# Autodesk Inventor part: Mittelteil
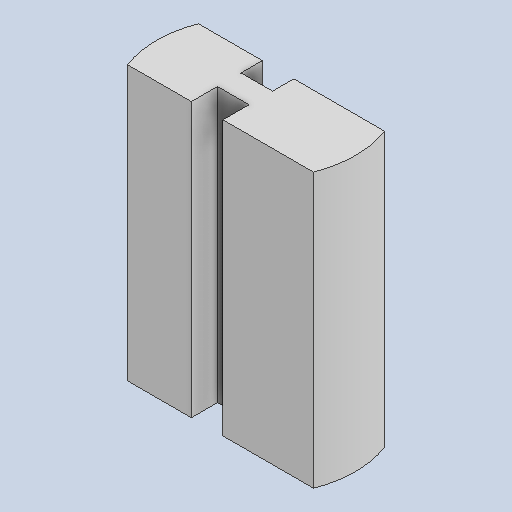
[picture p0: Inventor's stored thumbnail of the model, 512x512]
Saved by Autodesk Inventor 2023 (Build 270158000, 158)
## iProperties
Created: 2025-02
Part Number: Mittelteil
Material: Generisch
Document SubType Name: Modeling
Designer: MVM1
Density: 1 g/cm^3
Appearance: Vorgabe
Author: MVM1
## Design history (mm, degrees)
derived "Bauteil_Ohne_Scharnier.ipt"
feature "Mittelteil::Bauteil_Ohne_Scharnier.ipt" dims "d0" = 10
tag "Bezeichnung1"
node "Mittelteil"
